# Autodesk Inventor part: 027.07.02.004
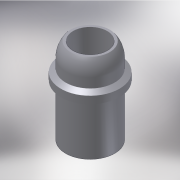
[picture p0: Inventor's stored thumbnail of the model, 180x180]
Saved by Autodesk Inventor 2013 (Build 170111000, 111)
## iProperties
Shininess: 25.0
Length Units: 11269
Angle Units: 11279
Time Units: 11290
Mass Units: 11283
Length Display Precision: 3
Angle Display Precision: 2
Created: 2001-11
Part Number: 027.07.02.004
Document SubType Name: Modeling
Designer: TEvgeniy
Material: Steel, Mild
Description: Ниппель
Density: 7.86 g/cm^3
Density: 0.0
Volumn: 0.0
Area: 0.0
PropertySet Name: Model Information
Control State: 0
Master: False
Checked Out: False
Checked Out Date: 2008-10-15
Last Check In Date: 2008-10-15
Author: TEvgeniy
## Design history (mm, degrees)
sketch "Sketch1"
  geometry: L1 (8, 17.5)-(7, 17.5); L2 (10, 7.655)-(10, 11.5); L3 (12, 6.5)-(10, 7.655); L4 (12, 3.5)-(12, 6.5); L5 (10, 3.5)-(12, 3.5); L6 (10, -17.5)-(10, 3.5); L7 (8.25, -17.5)-(10, -17.5); L8 (8.25, -14.5)-(8.25, -17.5); L9 (7, -14.5)-(8.25, -14.5); L10 (7, 17.5)-(7, -14.5); L11 (0, 24.085)-(0, -47.495); L12 (0, 24.085)-(0, -47.495); A1 r 10 centre (0, 11.5) between (10, 11.5) and (8, 17.5)
  constraints: 24 end point, 6 vertical, 4 horizontal, 2 point on circle, 1 centre point, 1 collinear, 1 tangent, 1 other
  dimensions: "d1" = 3 distance of L8.start L7.start; "d3" = 10 radius of A1; "d5" = 6 vertical distance of L1.end A1.centre; "d7" = 14 vertical distance of L1.end L4.start; "d9" = 3 distance of L3.start L4.start; "d11" = 60 deg angle of L3 L4; "d13" = 35 vertical distance of L1.end L6.start; "d15" = 8.25 horizontal distance of L7.start L11.end; "d17" = 7 horizontal distance of L9.start L11.end; "d19" = 10 horizontal distance of L6.start L11.start; "d21" = 12 horizontal distance of L4.start L11.start
revolve "RevolutionFull1" sketch "Sketch1" stored, may be unused: angle "d22" = 360 deg
body "Solid1"
other parameters: "d0" = 3 (derived), "d4" = 6 (derived), "d6" = 14 (derived), "d8" = 3 (derived), "d10" = 60 deg (derived), "d12" = 35 (derived), "d14" = 8.25 (derived), "d16" = 7 (derived), "d20" = 12 (derived)
